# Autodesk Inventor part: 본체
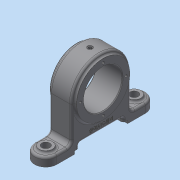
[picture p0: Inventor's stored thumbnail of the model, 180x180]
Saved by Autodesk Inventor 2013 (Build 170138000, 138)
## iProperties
Created: 2019-05
Part Number: 본체
Material: 일반
Document SubType Name: Modeling
Designer: dg
Density: 1 g/cm^3
Author: dg
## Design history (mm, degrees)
sketch "스케치1"
  geometry: L1 (18, 0)-(-18, 0); L2 (-18, 0)-(-18, 36); L3 (-18, 36)-(-15, 36); L4 (-15, 36)-(-15, 40); L5 (-15, 40)-(15, 40); L6 (15, 40)-(15, 36); L7 (15, 36)-(18, 36); L8 (18, 36)-(18, 0); L9 (18, 26)-(-18, 26); 2 further points
  constraints: 18 end point, 4 parallel, 3 perpendicular, 2 point on line, 1 coincident, 1 collinear, 1 horizontal, 1 midpoint
  dimensions: "d0" = 36 distance of L1.start L1.end; "d5" = 72 diameter of L3 L1; "d6" = 72 diameter of L7 L1; "d7" = 80 diameter of L5 L1; "d8" = 52 diameter of L9 L1; "d10" = 15 distance from line of point (0, 0) L6; "d11" = 15 distance from line of point (0, 0) L4
revolve "회전1" sketch "스케치1" stored, may be unused: angle "d12" = 90 deg
node "작업 평면1"
sketch "스케치2"
  geometry: L1 (-15, 60)-(15, 60); L2 (15, 60)-(15, -60); L3 (15, -60)-(-15, -60); L4 (-15, -60)-(-15, 60); A1 r 15 centre (0, -60) between (-15, -60) and (15, -60); A2 r 15 centre (0, 60) between (15, 60) and (-15, 60); 3 further points
  constraints: 8 end point, 4 point on circle, 4 tangent, 2 centre point, 2 midpoint, 2 parallel, 1 horizontal, 1 horizontal alignment, 1 perpendicular, 1 vertical alignment
  dimensions: "d14" = 30 distance of L2.end L3.end; "d15" = 120 distance of L1.end L2.end
extrude "돌출2" join sketch "스케치2" distance "d18" = 12; taper "d19" = 0 deg
sketch "스케치3"
  geometry: L1 (-4, 24)-(0, 24); L2 (0, 24)-(0, 96); L3 (0, 96)-(-4, 96); L4 (-4, 96)-(-4, 24); 3 further points
  constraints: 8 end point, 2 parallel, 1 horizontal, 1 horizontal alignment, 1 midpoint, 1 perpendicular, 1 vertical alignment
  dimensions: "d20" = 4 distance of L3.end L2.end; "d21" = 72 distance of L2.end L1.end
extrude "돌출3" cut sketch "스케치3" stored distance "d22" = 0; taper "d23" = 0 deg
sketch "스케치4"
  geometry: L1 (2, 30)-(8, 30); L2 (8, 30)-(8, 90); L3 (8, 90)-(2, 90); L4 (2, 90)-(2, 30); 3 further points
  constraints: 8 end point, 2 parallel, 1 horizontal, 1 horizontal alignment, 1 midpoint, 1 perpendicular, 1 vertical alignment
  dimensions: "d24" = 6 distance of L3.end L2.end; "d25" = 60 distance of L2.end L1.end
extrude "돌출4" cut sketch "스케치4" stored distance "d26" = 12; taper "d27" = 0 deg
sketch "스케치5"
  geometry: L1 (-15, 40)-(15, 40); L2 (15, 40)-(15, -40); L3 (15, -40)-(-15, -40); L4 (-15, -40)-(-15, 40); 3 further points
  constraints: 8 end point, 2 midpoint, 2 parallel, 1 horizontal, 1 horizontal alignment, 1 perpendicular, 1 vertical alignment
  dimensions: "d28" = 30 distance of L2.end L3.end; "d29" = 80 distance of L1.end L2.end
extrude "돌출5" join sketch "스케치5" stored distance "d30" = 12; taper "d31" = 0 deg
sketch "스케치6"
  geometry: C1 r 9 at (0, 60); C2 r 9 at (0, -60); A1 r 15 centre (0, -60) between (-15, -60) and (15, -60) reference; A2 r 15 centre (0, 60) between (15, 60) and (-15, 60) reference; 1 further point
  constraints: 2 centre point, 2 coincident
  dimensions: "d32" = 18 diameter of C1; "d33" = 18 diameter of C2
extrude "돌출6" join sketch "스케치6" distance "d34" = 3; taper "d35" = 0 deg
sketch "스케치7"
  geometry: C1 r 9 at (0, 0) reference; C2 r 9 at (0, 120) reference; 1 further point
hole "구멍1" sketch "스케치7" at (0, 0), (0, 120) diameter "d36" = 11; stored, may be unused: countersink angle "d40" = 90 deg, drill point angle "d42" = 118 deg; dims "d37" = 6, "d38" = 4, "d39" = 2, "d41" = 8
sketch "스케치8"
  geometry: C1 r 36 at (0, 0) reference; 1 further point
  constraints: 1 vertical alignment
  dimensions: "d43" = 31 distance of C1.centre point (0, 31)
hole "구멍2" sketch "스케치8" at (0, 31) diameter "d44" = 3.242; stored, may be unused: countersink angle "d48" = 90 deg, drill point angle "d50" = 118 deg; dims "d45" = 6, "d46" = 4, "d47" = 2, "d49" = 8
node "작업 평면2"
sketch "스케치9"
  geometry: C1 r 3.5 at (0, 0); 1 further point
  constraints: 1 centre point, 1 coincident
  dimensions: "d55" = 7 diameter of C1
extrude "돌출7" cut sketch "스케치9" distance "d56" = 1; taper "d57" = 0 deg
sketch "스케치10"
  geometry: C1 r 3.5 at (0, 0) reference
hole "구멍3" sketch "스케치10" at (0, 0) diameter "d58" = 4.917; stored, may be unused: countersink angle "d62" = 90 deg, drill point angle "d64" = 118 deg; dims "d59" = 7, "d60" = 4, "d61" = 2, "d63" = 9
fillet "모깎기1" dims "d65" = 6
fillet "모깎기2" dims "d66" = 3
fillet "모깎기3" dims "d67" = 3
fillet "모깎기4" dims "d68" = 3
chamfer "모따기1" distance "d69" = 1; stored, may be unused: second distance "d70" = 2, angle "d71" = 45 deg
sketch "스케치12"
  geometry: C1 r 1.5 at (-26, 0); 1 further point
  constraints: 1 centre point, 1 horizontal alignment, 1 other
  dimensions: "d72" = 3 diameter of C1
extrude "돌출8" cut sketch "스케치12" stored distance "d73" = 1; taper "d74" = 0 deg
sketch "스케치13"
  geometry: L1 (-10, 33)-(-10, 87) reference; A1 r 39 centre (-60, 60) between (-47.671, 23) and (-47.671, 97) reference; 1 further point
  constraints: 1 horizontal alignment, 1 other
  dimensions: "d75" = 7 distance from line of L1 point (-17, 60)
feature "엠보싱1" sketch "스케치13" dims "d0" = 36, "d5" = 72, "d6" = 72, "d7" = 80, "d8" = 52, "d10" = 15, "d11" = 15, "d18" = 12, "d76" = 0.5, "d77" = 0
sketch "스케치15"
  geometry: C1 r 3.5 at (0, 0) reference; C2 r 1 at (0, 0)
  constraints: 1 centre point, 1 coincident
  dimensions: "d81" = 2 diameter of C2
extrude "돌출10" cut sketch "스케치15" stored distance "d82" = 10; taper "d83" = 0 deg
node "솔리드1"
pattern_circular "원형 패턴1" dims angle "d52" = 360 deg
mirror "대칭1"
